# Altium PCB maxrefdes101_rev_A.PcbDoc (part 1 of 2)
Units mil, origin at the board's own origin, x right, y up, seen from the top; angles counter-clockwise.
Board outline 1192.91 x 1079.23 mil, 4 copper layers (Top Layer, Power Plane, Ground Plane, Bottom Layer), stack 32.372 mil thick; 87 components, 63 nets, 389 pads, 163 vias.
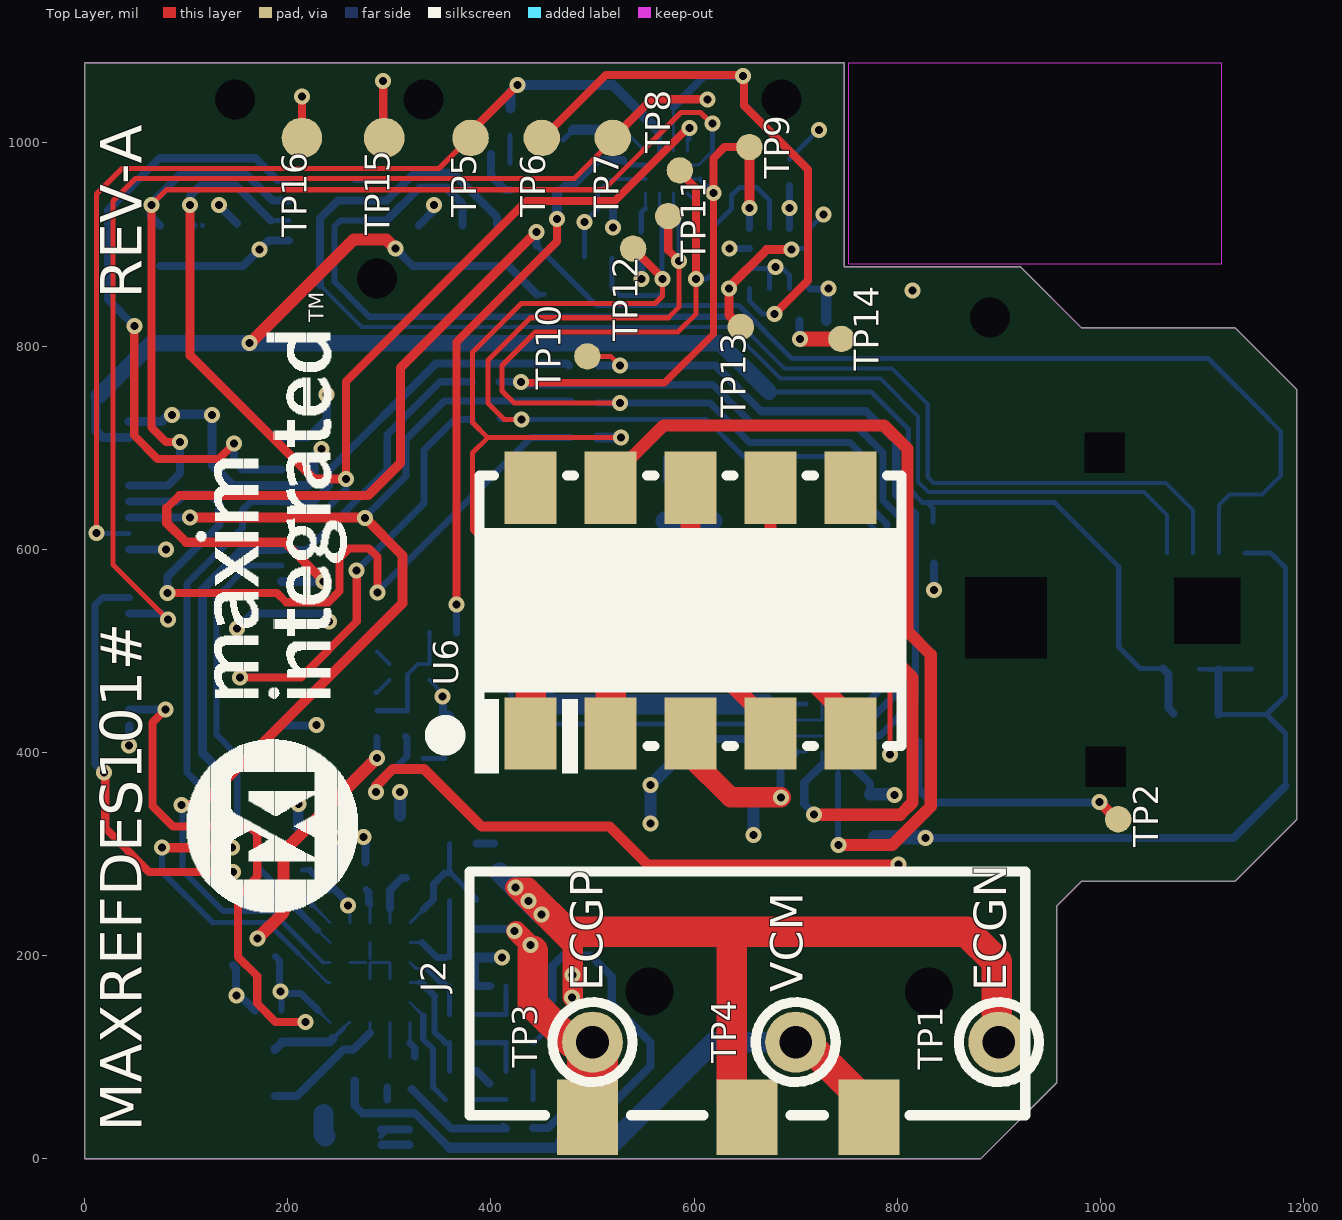
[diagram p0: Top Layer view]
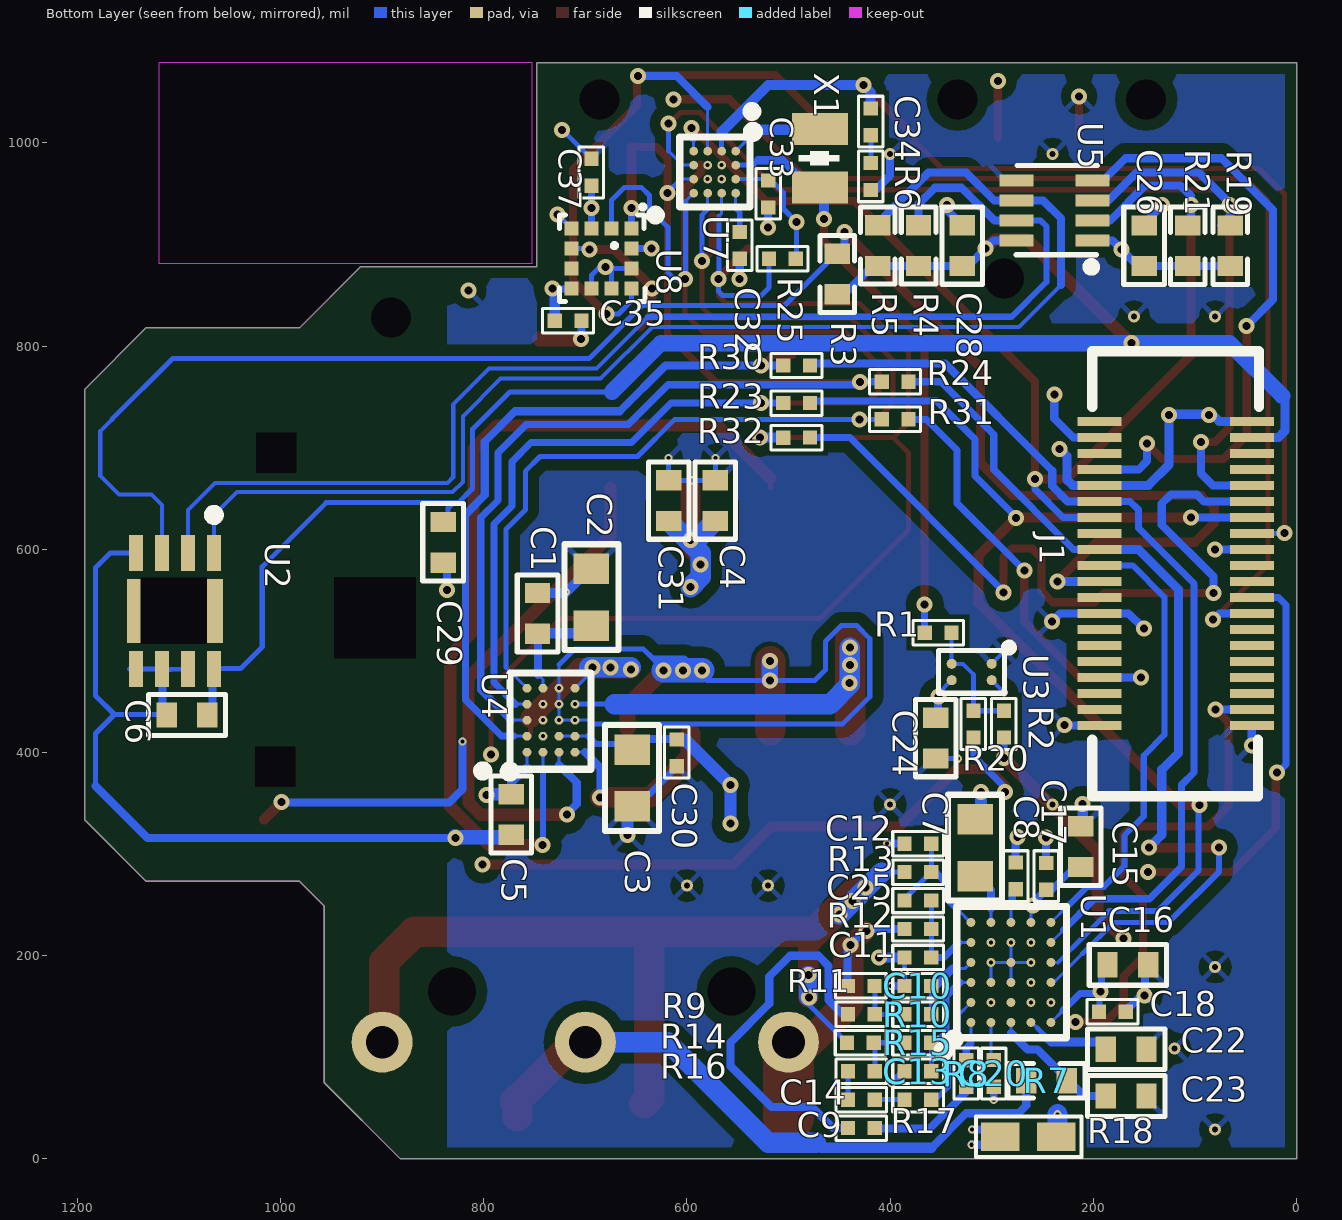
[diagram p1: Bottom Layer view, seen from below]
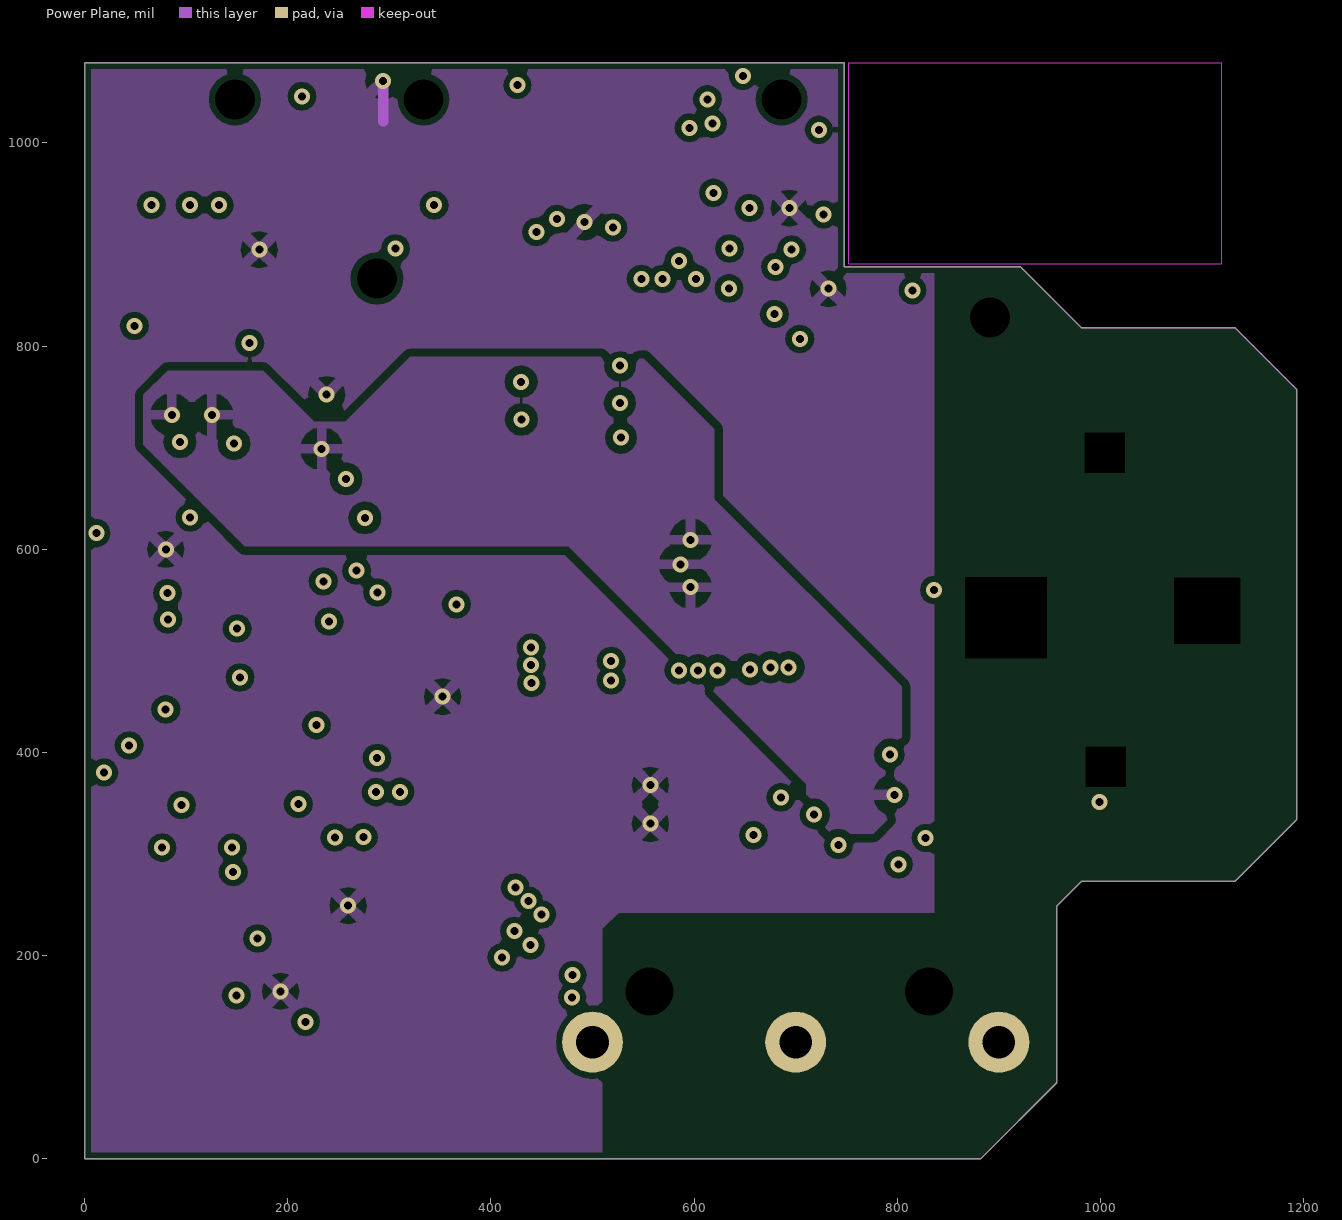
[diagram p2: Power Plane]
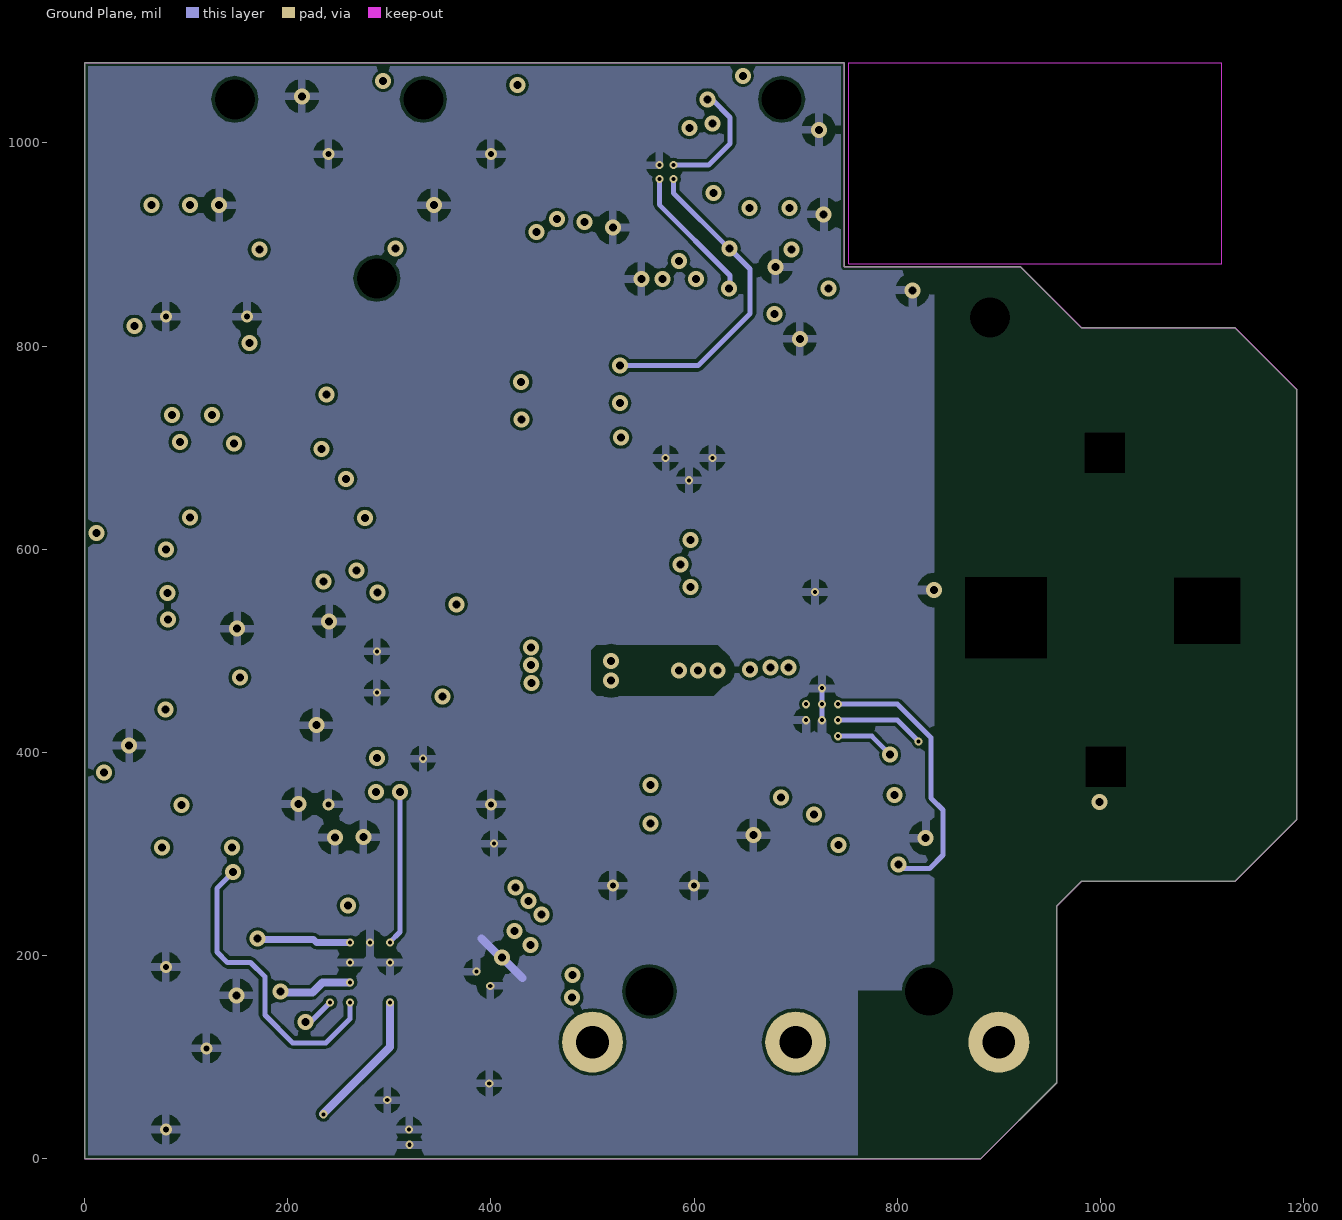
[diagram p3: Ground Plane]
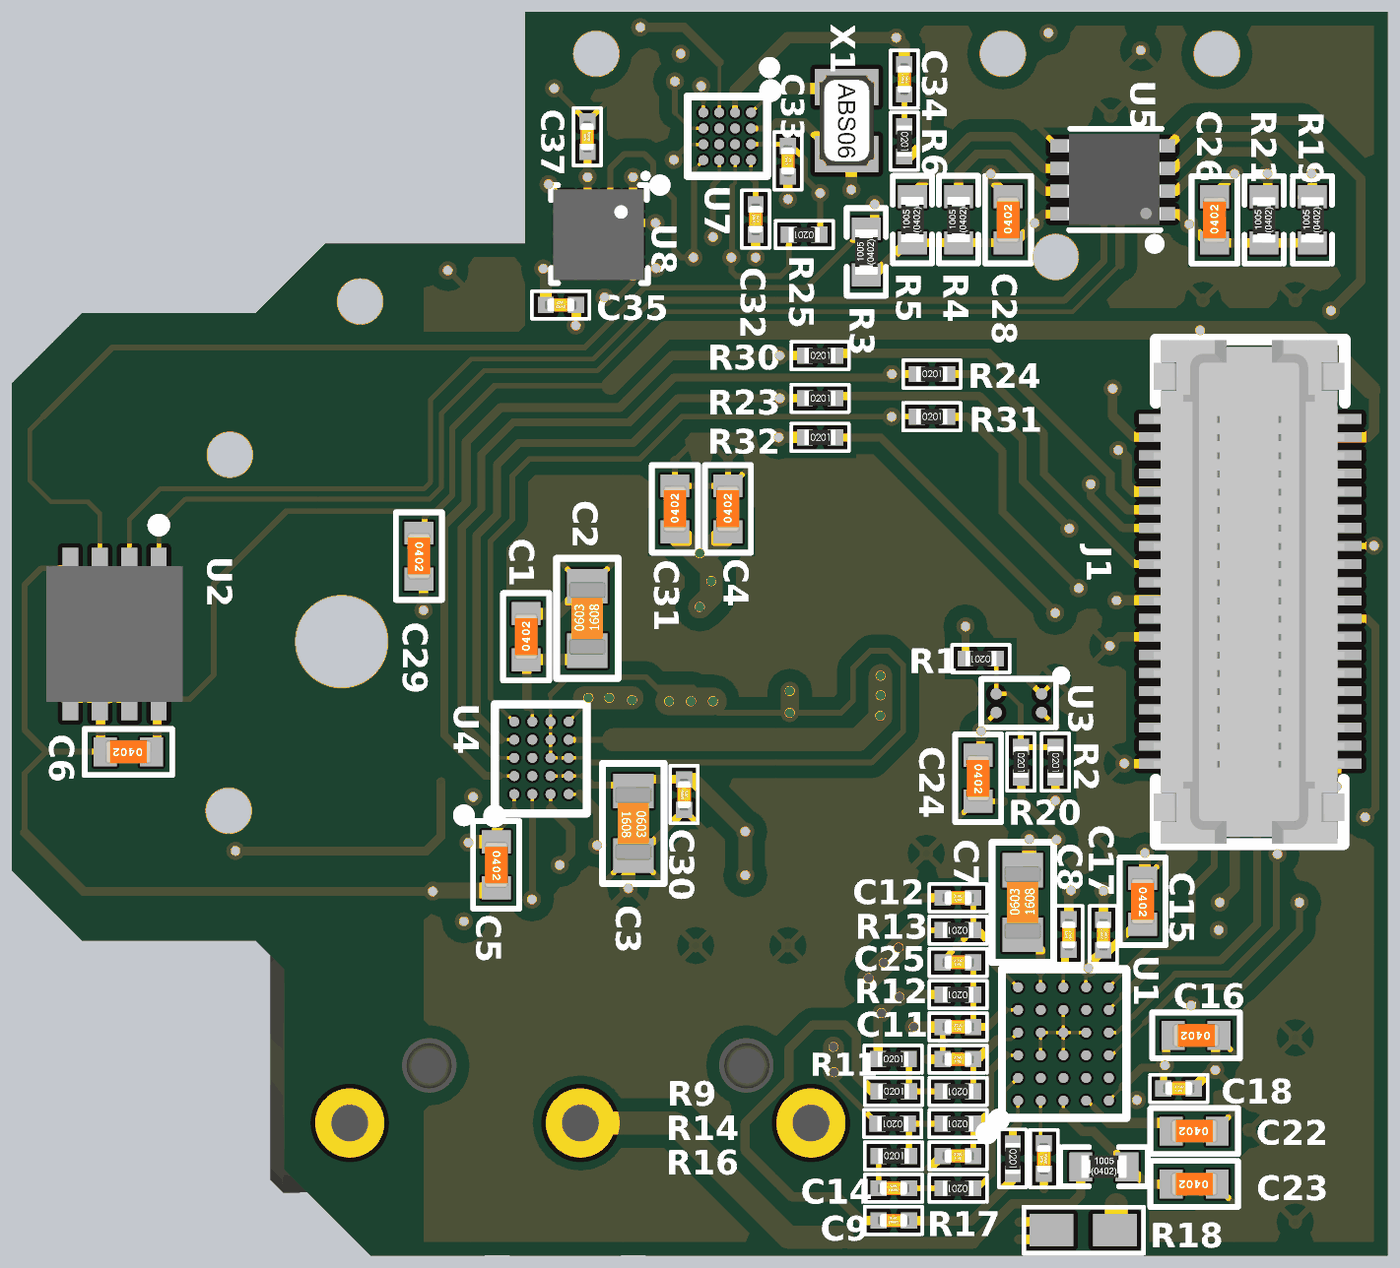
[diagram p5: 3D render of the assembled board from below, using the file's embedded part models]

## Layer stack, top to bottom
Top Solder: solder mask 0.4, Solder Resist, Dk 3.5
Top Layer: signal copper 1.4
Dielectric1: prepreg 6.8898, FR-4, Dk 4.2
Power Plane: signal copper 1.4
Dielectric2: core 12.9921, FR-4, Dk 4.2
Ground Plane: signal copper 1.4
Dielectric5: prepreg 6.8898, FR-4, Dk 4.2
Bottom Layer: signal copper 1.4
Bottom Solder: solder mask 0.4, Solder Resist, Dk 3.5

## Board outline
0,0 0,1079.23 748,1079.23 748,878.39 920.91,878.39 981.39,817.91 1132.39,817.91 1192.91,757.39 1192.91,333.91 1132.39,273.39 981.39,273.39 957,249 957,75 882,0

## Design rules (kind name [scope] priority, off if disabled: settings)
Clearance Clearance_2 [InNamedPolygon('COMPONENT_GND')] p1: gap=11 ignorepadtopadclearanceinfootprint=FALSE except(0: Arc-Hole Track-Hole SMDPad-Hole THPad-Hole Via-Hole Fill-Hole Poly-Hole Region-Hole Text-Hole)
Clearance Clearance_1 [InNamedPolygon('PLANE_5V')] p2: gap=8 ignorepadtopadclearanceinfootprint=FALSE except(0: Arc-Hole Track-Hole SMDPad-Hole THPad-Hole Via-Hole Fill-Hole Poly-Hole Region-Hole Text-Hole)
Clearance Clearance_PD_Shield [InNamedPolygon('PLANE_1V8')] p3: gap=6 ignorepadtopadclearanceinfootprint=FALSE except(0: Arc-Hole Track-Hole SMDPad-Hole THPad-Hole Via-Hole Fill-Hole Poly-Hole Region-Hole Text-Hole)
Clearance "Clearance_Bottom Layer" [OnLayer('Bottom Layer')] p4: gap=5 ignorepadtopadclearanceinfootprint=FALSE except(0: Arc-Hole Track-Hole SMDPad-Hole THPad-Hole Via-Hole Fill-Hole Poly-Hole Region-Hole Text-Hole)
Clearance "Clearance Power Plane" [OnLayer('Power Plane 1.8v')] p5: gap=5 ignorepadtopadclearanceinfootprint=FALSE except(0: Arc-Hole Track-Hole SMDPad-Hole THPad-Hole Via-Hole Fill-Hole Poly-Hole Region-Hole Text-Hole)
Clearance "Clearance Ground Plane" [(OnLayer('Ground Plane +') AND InNamedPolygon('GND'))] p6: gap=5 ignorepadtopadclearanceinfootprint=FALSE except(0: Arc-Hole Track-Hole SMDPad-Hole THPad-Hole Via-Hole Fill-Hole Poly-Hole Region-Hole Text-Hole)
Clearance [All] p7: gap=3 ignorepadtopadclearanceinfootprint=FALSE except(0: Arc-Hole Track-Hole SMDPad-Hole THPad-Hole Via-Hole Fill-Hole Poly-Hole Region-Hole Text-Hole)
ComponentClearance [All] p1: gap=0 collisioncheckmode=3 verticalgap=0 showdistances=FALSE
HoleSize [All] p1: absolutevalues=TRUE maxlimit=500 minlimit=4 maxpercent=80.000 minpercent=20.000
HoleToHoleClearance [All] p1: gap=9 allowstackedmicrovias=TRUE
MinimumAnnularRing [All] p1: minimumring=2
MinimumSolderMaskSliver [All] p1: minsoldermaskwidth=0
PlaneConnect [All] p1: planeconnectstyle=Relief reliefexpansion=20 reliefentries=4 reliefconductorwidth=7 reliefairgap=10
PolygonConnect PolygonConnect_5 [All vs IsNamedPolygon('PLANE_5V')] p1: connectstyle=Relief reliefconductorwidth=10 reliefentries=4 polygonreliefangle="90 Angle" airgapwidth=13
PolygonConnect PolygonConnect_4 [All vs IsNamedPolygon('PLANE_GROUND')] p2: connectstyle=Relief reliefconductorwidth=8 reliefentries=4 polygonreliefangle="90 Angle" airgapwidth=9
PolygonConnect PolygonConnect_3 [All vs IsNamedPolygon('PP_5V')] p3: connectstyle=Relief reliefconductorwidth=14 reliefentries=4 polygonreliefangle="90 Angle" airgapwidth=10
PolygonConnect PolygonConnect_2 [All vs IsNamedPolygon('PP_1V8')] p4: connectstyle=Relief reliefconductorwidth=10 reliefentries=4 polygonreliefangle="90 Angle" airgapwidth=8
PolygonConnect PolygonConnect_1 [All vs IsNamedPolygon('PLANE_1V8')] p5: connectstyle=Relief reliefconductorwidth=11 reliefentries=4 polygonreliefangle="45 Angle" airgapwidth=10
PolygonConnect [All] p6: connectstyle=Relief reliefconductorwidth=5 reliefentries=4 polygonreliefangle="45 Angle" airgapwidth=10
RoutingVias [All] p1: holewidth=8 width=16 viastyle="Through Hole" minholewidth=4 minwidth=8 maxholewidth=28 maxwidth=50
SilkToSilkClearance [All] p1: silktosilkclearance=0
SilkToSolderMaskClearance SilkscreenOverComponentPads [IsPad] p1: minsilkscreentomaskgap=4 clearancetoexposedcopper=TRUE
SolderMaskExpansion [All] p1: expansion=4
Width [All] p1: maxlimit=100 minlimit=3 preferedwidth=5 minimp=50.000000 maximp=50.000000 favimp=50.000000
23 further rules are at their usual default settings.

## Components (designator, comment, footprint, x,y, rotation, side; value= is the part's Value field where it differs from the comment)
C1 "10u" CAPACITOR_SMD_0402 747,517 r90 bottom
C2 "1u" CAPACITOR_SMD_0603 694,553 r90 bottom
C3 "100n" CAPACITOR_SMD_0603 654,375 r270 bottom
C4 "22u" CAPACITOR_SMD_0402 572,628 r90 bottom
C5 "22u" CAPACITOR_SMD_0402 773,359 r270 bottom
C6 "100n" CAPACITOR_SMD_0402 1072,437 r0 bottom
C7 "1u" CAPACITOR_SMD_0603 316.39,306.39 r90 bottom
C8 "1n" CAPACITOR_SMD_0201 276.39,265.39 r90 bottom
C9 "47p" CAPACITOR_SMD_0201 441.39,30.39 r180 bottom
C10 "10p" CAPACITOR_SMD_0201 359.39,170.39 r0 bottom
C11 "10p" CAPACITOR_SMD_0201 359.39,198.39 r0 bottom
C12 "10p" CAPACITOR_SMD_0201 359.39,310.39 r0 bottom
C13 "10p" CAPACITOR_SMD_0201 359.39,86.39 r0 bottom
C14 "47n" CAPACITOR_SMD_0201 441.39,58.39 r180 bottom
C15 "10u" CAPACITOR_SMD_0402 212.39,327.39 r270 bottom
C16 "10u" CAPACITOR_SMD_0402 146,191 r0 bottom
C17 "100n" CAPACITOR_SMD_0201 246.4,291.39 r270 bottom
C18 "100n" CAPACITOR_SMD_0201 168,145 r0 bottom
C20 "1u" CAPACITOR_SMD_0201 298,71 r90 bottom
C22 "10u" CAPACITOR_SMD_0402 147.62,108 r0 bottom
C23 "10u" CAPACITOR_SMD_0402 147.62,62 r0 bottom
C24 "100n" CAPACITOR_SMD_0402 355,434.19 r270 bottom
C25 "1000p C0G" CAPACITOR_SMD_0201 359.39,254.39 r0 bottom
C26 "100n" CAPACITOR_SMD_0402 150,878.87 r90 bottom
C28 "100n" CAPACITOR_SMD_0402 329.07,879 r90 bottom
C29 "10u" CAPACITOR_SMD_0402 840,627 r270 bottom
C30 "1u" CAPACITOR_SMD_0201 610,413 r270 bottom
C31 "22u" CAPACITOR_SMD_0402 618,628 r90 bottom
C32 "1u" CAPACITOR_SMD_0201 548,912.39 r270 bottom
C33 "1u" CAPACITOR_SMD_0201 520,963 r270 bottom
C34 "1u" CAPACITOR_SMD_0201 419,1034 r270 bottom
C35 "100n" CAPACITOR_SMD_0201 730,825 r180 bottom
C37 "100n" CAPACITOR_SMD_0201 694,958 r90 bottom
J1 "500913-0402" 500913-0402_MRR 194,726 r270 bottom (schematic designator J10)
J2 "SJ2-3573A2-SMT-TR" CONN_SJ2-3573A2-SMT-TR 772,33 r180 top
R1 "0R" RESISTOR_SMD_0201 352.78,518 r0 bottom
R2 "0R" RESISTOR_SMD_0201 288,428 r270 bottom
R3 "3K3" RESISTOR_SMD_0402 452,851 r90 bottom
R4 "3K3" RESISTOR_SMD_0402 372,879 r90 bottom
R5 "3K3" RESISTOR_SMD_0402 412,879 r90 bottom
R6 "10R" RESISTOR_SMD_0201 419,967 r270 bottom
R7 "499K" RESISTOR_SMD_0402 266,77 r180 bottom
R8 "0R" RESISTOR_SMD_0201 325,84 r270 bottom
R9 "0R" RESISTOR_SMD_0201 428.19,142.39 r180 bottom
R10 "2K49" RESISTOR_SMD_0201 372.58,142.39 r0 bottom
R11 "0R" RESISTOR_SMD_0201 428.58,170.39 r180 bottom
R12 "1M" RESISTOR_SMD_0201 372.58,226.39 r0 bottom
R13 "1M" RESISTOR_SMD_0201 372.58,282.39 r0 bottom
R14 "0R" RESISTOR_SMD_0201 429.19,114.39 r0 bottom
R15 "2K49" RESISTOR_SMD_0201 372.58,114.39 r0 bottom
R16 "0R" RESISTOR_SMD_0201 428.19,86.39 r180 bottom
R17 "0R" RESISTOR_SMD_0201 372.58,58.39 r0 bottom
R18 "324K" RESISTOR_SMD_0603 236.46,22 r0 bottom
R19 "3K3" RESISTOR_SMD_0402 65.14,878.87 r90 bottom
R20 "0R" RESISTOR_SMD_0201 318,428 r270 bottom
R21 "3K3" RESISTOR_SMD_0402 107,878.87 r90 bottom
R23 "0R" RESISTOR_SMD_0201 492,744 r180 bottom
R24 "0R" RESISTOR_SMD_0201 395,765 r180 bottom
R25 "10K" RESISTOR_SMD_0201 506,886 r0 bottom
R30 "0R" RESISTOR_SMD_0201 492,781 r180 bottom
R31 "0R" RESISTOR_SMD_0201 395,728 r180 bottom
R32 "0R" RESISTOR_SMD_0201 492,710 r180 bottom
TP1 "ECG_N" TESTPOINT_SIZE_A_NO_BODY 900,115 r0 top
TP2 "TestPoint" TESTPOINT_SIZE_B#1 1017.39,334.39 r270 top
TP3 "ECG_P" TESTPOINT_SIZE_A_NO_BODY 500,115 r0 top
TP4 "VCM" TESTPOINT_SIZE_A_NO_BODY 700,115 r0 top
TP5 "RSTN" TESTPOINT_SIZE_C#1 380,1005 r90 top
TP6 "TestPoint" TESTPOINT_SIZE_C#1 450,1005 r90 top
TP7 "TestPoint" TESTPOINT_SIZE_C#1 520,1005 r90 top
TP8 "TestPoint" TESTPOINT_SIZE_B#1 586,973 r90 top
TP9 "TestPoint" TESTPOINT_SIZE_B#1 654.39,996 r90 top
TP10 "TestPoint" TESTPOINT_SIZE_B#1 495,790 r90 top
TP11 "TestPoint" TESTPOINT_SIZE_B#1 574.56,928 r90 top
TP12 "TestPoint" TESTPOINT_SIZE_B#1 540,896.07 r90 top
TP13 "TestPoint" TESTPOINT_SIZE_B#1 646,819 r90 top
TP14 "TestPoint" TESTPOINT_SIZE_B#1 745,807.19 r90 top
TP15 "TestPoint" TESTPOINT_SIZE_C#2 295,1005 r90 top (schematic designator TP5)
TP16 "TestPoint" TESTPOINT_SIZE_B#2 214,1005 r90 top
U1 "MAX30001CWV+" "WLP30 0.5MM" 320.39,134.39 r90 bottom
U2 "MAX30205MTA+" TDFN_3x3mm 1104,539.39 r270 bottom
U3 "SIT1532AC-J5-DCC-32.768E" CSP_1.55x0.85_4pin 300,487.39 r270 bottom
U4 "MAX86140/1" WLP20_0.4MM 733.77,431.89 r90 bottom
U5 "MAX14595ETA+T" TDFN8 201,904 r90 bottom
U6 "LED_MODULE" HSP3_LEDMODULE_03 438.98,418.61 r90 top locked
U7 "MAX32664GWEZ+" WLP16_0.35mm 552,992 r270 bottom
U8 "KX122-1037" LGA-12_2x2x0.9 654.39,916 r270 bottom (schematic designator U9)
X1 "32.768KHz" CRYSTAL_2x1.2mm 469,1016 r270 bottom

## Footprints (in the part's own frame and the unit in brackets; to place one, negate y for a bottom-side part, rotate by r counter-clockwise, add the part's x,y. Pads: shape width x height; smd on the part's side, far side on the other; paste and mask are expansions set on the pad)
500913-0402_MRR [mm] "0.40mm Pitch SlimStack™ Board-to-Board Receptacle, Surface Mount, Dual Row, Vertical Stacking, Mated Height of 1.80mm, with Solder Tabs, 40 Circuits"
  rect 0.22x1.1 smd: 1(0,0) 2(0,3.81) 3(0.4,0) 4(0.4,3.81) 5(0.8,0) 6(0.8,3.81) 7(1.2,0) 8(1.2,3.81) 9(1.6,0) 10(1.6,3.81) 11(2,0) 12(2,3.81) 13(2.4,0) 14(2.4,3.81) 15(2.8,0) 16(2.8,3.81) 17(3.2,0) 18(3.2,3.81) 19(3.6,0) 20(3.6,3.81) 21(4,0) 22(4,3.81) 23(4.4,0) 24(4.4,3.81) 25(4.8,0) 26(4.8,3.81) 27(5.2,0) 28(5.2,3.81) 29(5.6,0) 30(5.6,3.81) 31(6,0) 32(6,3.81) 33(6.4,0) 34(6.4,3.81) 35(6.8,0) 36(6.8,3.81) 37(7.2,0) 38(7.2,3.81) 39(7.6,0) 40(7.6,3.81)
  silkscreen extent -1.75,-0.18 9.37,3.99, body extent -1.74,-0.22 9.36,3.98, height 1.69
CAPACITOR_SMD_0201 [mil] "SMD 0201 Chip Capacitor"
  rect 14x14 smd: 1(0,0) 2(26.39,0)
  silkscreen extent -12,-12 38,12, body extent -4,-6 30,6, height 12
CAPACITOR_SMD_0402 [mil] "0402 SMD Ceramic Capacitor"
  rect 20x25 smd mask+2: 1(0,0) 2(40,0)
  silkscreen extent -18,-20 58,20, body extent 0,-10 40,10, height 20
CAPACITOR_SMD_0603 [mil] "SMD 0603 Chip Capacitor"
  rect 30x35 smd mask+2: 1(-28,0) 2(28,0)
  silkscreen extent -52,-27 52,27, body extent -31,-16 31,16, height 31
CONN_SJ2-3573A2-SMT-TR [mil] "SJ2-3573A2-SMT-TR AUDIO JACK, 3.5 MM, RT, 3 CONDUC"
  round 0 hole 47.24 unplated: 0(-59,-132) 0(216,-132)
  rect 60x74 smd: 1(0,-8) 2(120,-8) 3(277,-8)
  silkscreen extent -154,-250 393,-10, body extent -197,-250 394,34, height 211
CRYSTAL_2x1.2mm [mm] "Abracon 2 lead crystal (2.00mm x 1.20mm)"
  rect 0.8x1.4 smd: 1(0.051,0) 2(1.524,0)
  silkscreen extent 0.61,-0.53 0.97,0.48, body extent -0.21,-0.61 1.79,0.61, height 0.6
CSP_1.55x0.85_4pin [mm] "1.55mm x 0.85mm 4 pin CSP Package"
  round 0.25 smd: 1(0,0) 2(0,-1) 3(0.41,-1) 4(0.41,0)
  silkscreen extent -0.48,-1.33 0.74,0.51, body extent -0.23,-1.27 0.64,0.28, height 0.6
HSP3_LEDMODULE_03 [mm] "LED Module for HSP3.0 (0.6mm PCB Thickness)"
  rect 1.8x1.3 smd: 1(0,0) 2(0,-2) 3(0,-4) 4(0,-6) 5(0,-8)
  rect 1.815x1.3 smd: 6(6.147,-8) 7(6.147,-6) 8(6.147,-4) 9(6.147,-2) 10(6.147,0)
  silkscreen extent -0.99,-9.27 6.45,1.4, body extent -0.3,-9.19 6.45,1.17, height 1.2
LGA-12_2x2x0.9 [mm] "LGA-12_2x2x0.9 SMD Package For Kionix KX122-1037 Accelerometer"
  rect 0.35x0.35 smd: 1(0,0) 2(0,-0.5) 3(0,-1) 4(0,-1.5) 5(0.5,-1.5) 6(1,-1.5) 7(1.5,-1.5) 8(1.5,-1) 9(1.5,-0.5) 10(1.5,0) 11(1,0) 12(0.5,0)
  silkscreen extent -0.58,-1.8 1.83,0.33, body extent -0.24,-1.76 1.76,0.24, height 0.95
RESISTOR_SMD_0201 [mil] "SMD 0201 Chip Resistor"
  rect 14x14 smd: 1(-13.19,0) 2(13.19,0)
  silkscreen extent -25,-12 25,12, body extent -14,-6 13,6, height 13
RESISTOR_SMD_0402 [mil] "SMD 0201 Chip Resistor"
  rect 20x25 smd mask+2: 1(0,0) 2(40,0)
  silkscreen extent -18,-17 58,17, body extent 0,-10 40,10, height 14
RESISTOR_SMD_0603 [mil] "SMD 0603 Chip Resistor"
  rect 38x28 smd: 1(0,0) 2(55,0)
  silkscreen extent -25,-20 79,20, body extent -9,-18 63,18, height 18
TDFN8 [mm] "TDFN8 2x2x0.75mm"
  rect 0.3x0.85 smd: 1(0,0) 2(0.5,0) 3(1,0) 4(1.5,0) 5(1.5,1.9) 6(1,1.9) 7(0.5,1.9) 8(0,1.9)
  silkscreen extent -0.75,-0.13 1.88,1.91, body extent -0.24,-0.11 1.76,1.94, height 0.75
TDFN_3x3mm [mm] "SON, 0.65mm pitch, 8 pin, 3mm X 3mm X 1.00mm H body (w/thermal tab 1.60 X 2.4mm),  IPC Medium Density"
  rect 0.9x0.35 smd: 1(-1.45,0.975) 2(-1.45,0.325) 3(-1.45,-0.325) 4(-1.45,-0.975) 5(1.45,-0.975) 6(1.45,-0.325) 7(1.45,0.325) 8(1.45,0.975)
  rect 1.6x2.4 smd: 9(0,0)
  silkscreen extent -2.52,0.85 -2.28,1.1, body extent -1.5,-1.5 1.5,1.5, height 1
TESTPOINT_SIZE_A_NO_BODY [mil] "32 mil testpoint pad"
  round 60 hole 32: TP(0,0)
  silkscreen extent -39,-39 39,39
TESTPOINT_SIZE_B#1 [mil] "32 mil testpoint pad"
  round 26 smd: TP(0,0)
  body extent -2,-2 2,2, height 1
TESTPOINT_SIZE_B#2 [mil] "SMD testpoint pad"
  round 40 smd: TP(0,0)
  body extent -2,-2 2,2, height 1
TESTPOINT_SIZE_C#1 [mil] "SMD testpoint pad"
  round 36 smd: TP(0,0)
  body extent -2,-2 2,2, height 1
TESTPOINT_SIZE_C#2 [mil] "SMD testpoint pad"
  round 40 smd: TP(0,0)
  body extent -2,-2 2,2, height 1
WLP16_0.35mm [mm] "WLP-16,  1.6mm x 1.6mm, 0.35mm pitch"
  round 0.22 smd mask+0.05: A1(0,0) A2(0.35,0) A3(0.7,0) A4(1.05,0) B1(0,-0.35) B2(0.35,-0.35) B3(0.7,-0.35) B4(1.05,-0.35) C1(0,-0.7) C2(0.35,-0.7) C3(0.7,-0.7) C4(1.05,-0.7) D1(0,-1.05) D2(0.35,-1.05) D3(0.7,-1.05) D4(1.05,-1.05)
  round 0.025 on Mech4 mask+0.051: ""(-0.022,-0.022) ""(-0.022,0.022) ""(0.022,-0.022) ""(0.022,0.022)
  silkscreen extent -0.61,-1.4 1.4,0.56, body extent -0.18,-1.22 1.22,0.18, height 0.63
WLP20_0.4MM [mil] "WLP-20,  5x4, 0.4mm pitch"
  round 8.66 smd mask+1.97: A1(-31.5,23.62) A2(-15.75,23.62) A3(0,23.62) A4(15.75,23.62) A5(31.5,23.62) B1(-31.5,7.87) B2(-15.75,7.87) B3(0,7.87) B4(15.75,7.87) B5(31.5,7.87) C1(-31.5,-7.87) C2(-15.75,-7.87) C3(0,-7.87) C4(15.75,-7.87) C5(31.5,-7.87) D1(-31.5,-23.62) D2(-15.75,-23.62) D3(0,-23.62) D4(15.75,-23.62) D5(31.5,-23.62)
  round 1 on Mech4 mask+2: ""(-32.38,-24.51) ""(-32.38,-8.76) ""(-32.38,6.99) ""(-32.38,22.74) ""(-32.38,-22.74) ""(-32.38,-6.99) ""(-32.38,8.76) ""(-32.38,24.51) ""(-30.61,-24.51) ""(-30.61,-22.74) ""(-30.61,-8.76) ""(-30.61,-6.99) ""(-30.61,6.99) ""(-30.61,8.76) ""(-30.61,22.74) ""(-30.61,24.51) ""(-16.63,-24.51) ""(-16.63,-8.76) ""(-16.63,6.99) ""(-16.63,22.74) ""(-16.63,-22.74) ""(-16.63,-6.99) ""(-16.63,8.76) ""(-16.63,24.51) ""(-14.86,-24.51) ""(-14.86,-22.74) ""(-14.86,-8.76) ""(-14.86,-6.99) ""(-14.86,6.99) ""(-14.86,8.76) ""(-14.86,22.74) ""(-14.86,24.51) ""(-0.88,-24.51) ""(-0.88,-8.76) ""(-0.88,6.99) ""(-0.88,22.74) ""(-0.88,-22.74) ""(-0.88,-6.99) ""(-0.88,8.76) ""(-0.88,24.51) ""(0.88,-24.51) ""(0.88,-22.74) ""(0.88,-8.76) ""(0.88,-6.99) ""(0.88,6.99) ""(0.88,8.76) ""(0.88,22.74) ""(0.88,24.51) ""(14.86,-24.51) ""(14.86,-8.76) ""(14.86,6.99) ""(14.86,22.74) ""(14.86,-22.74) ""(14.86,-6.99) ""(14.86,8.76) ""(14.86,24.51) ""(16.63,-24.51) ""(16.63,-22.74) ""(16.63,-8.76) ""(16.63,-6.99) ""(16.63,6.99) ""(16.63,8.76) ""(16.63,22.74) ""(16.63,24.51) ""(30.61,-24.51) ""(30.61,-8.76) ""(30.61,6.99) ""(30.61,22.74) ""(30.61,-22.74) ""(30.61,-6.99) ""(30.61,8.76) ""(30.61,24.51) ""(32.38,-24.51) ""(32.38,-22.74) ""(32.38,-8.76) ""(32.38,-6.99) ""(32.38,6.99) ""(32.38,8.76) ""(32.38,22.74) ""(32.38,24.51)
  silkscreen extent -55,-39 47,46, body extent -38,-30 39,31, height 25
"WLP30 0.5MM" [mm] "WLP 30 0.5mm Pitch"
  round 0.22 smd mask+0.05: A1(0,0) A2(0.5,0) A3(1,0) A4(1.5,0) A5(2,0) A6(2.5,0) B1(0,-0.5) B2(0.5,-0.5) B3(1,-0.5) B4(1.5,-0.5) B5(2,-0.5) B6(2.5,-0.5) C1(0,-1) C2(0.5,-1) C3(1,-1) C4(1.5,-1) C5(2,-1) C6(2.5,-1) D1(0,-1.5) D2(0.5,-1.5) D3(1,-1.5) D4(1.5,-1.5) D5(2,-1.5) D6(2.5,-1.5) E1(0,-2) E2(0.5,-2) E3(1,-2) E4(1.5,-2) E5(2,-2) E6(2.5,-2)
  round 0.025 on Mech4 mask+0.051: ""(-0.022,-0.022) ""(-0.022,0.022) ""(0.022,-0.022) ""(0.022,0.022)
  silkscreen extent -0.84,-2.38 2.9,0.81, body extent -0.18,-2.18 2.67,0.18, height 0.63

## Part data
C1 C15 C16 C22 C23 C29: library part CAP_0402_10u, "CAP CER 10UF 4V X5R 0402"
C2 C7: library part CAP_0603_1u, "CAP CER 1UF 16V X5R 0603"
C3: library part CAP_0603_100n, "CAP CER 0.1UF 16V X7R 0603"
C4 C5 C31: library part CAP_0402_22U, "CAP CER 22UF 6.3V X5R 0402"
C6 C24 C26 C28: library part CAP_0402_100n, "CAP CER 0.1UF 16V X7R 0402"
C8: library part CAP_0201_1n, "CAP CER 1000PF 16V X7R 0201"
C9: library part CAP_0201_47p, "CAP CER 47PF 25V C0G/NP0 0201"
C10 C11 C12 C13: library part CAP_0201_10p, "CAP CER 10PF 25V C0G/NP0 0201"
C14: library part CAP_0201_47n, "CAP CER 0.047UF 16V X5R 0201"
C17 C18 C35 C37: library part CAP_0201_100n, "CAP CER 0.1UF 10V X5R 0201"
C20 C30 C32 C33 C34: library part CAP_0201_1u, "CAP CER 1UF 10V X6S 0201"
C25: library part CAP_0201_1000p, "CAP CER 1000PF 25V C0G/NP0 0201"
J1: library part MOLEX_5009130402, "CONN RCPT 40POS 0.4MM SMD GOLD"
J2: "AUDIO JACK, 3.5 MM, RT, 3 CONDUC"
R1 R2 R8 R9 R11 R14 R16 R17 R20 R23 R24 R30 R31 R32: library part RES_0201_0R, "RES SMD 0 OHM JUMPER 1/20W 0201"
R3 R4 R5 R19 R21: library part RES_0402_3K3, "RES SMD 3.3K OHM 1% 1/10W 0402"
R6: library part RES_0201_10R, "RES SMD 10 OHM 1% 1/20W 0201"
R7: library part RES_0402_499K, "RES SMD 49.9K OHM 1% 1/10W 0402"
R10 R15: library part RES_0201_2K49, "RES SMD 2.49K OHM 1% 1/20W 0201"
R12 R13: library part RES_0201_1M, "RES SMD 1M OHM 1% 1/20W 0201"
R18: library part RES_0603_324K%0.1_10ppm, "RES SMD 324K OHM 0.1% 1/16W 0603"
R25: library part RES_0201_10K, "RES SMD 10K OHM 1% 1/20W 0201"
TP1 TP3 TP4 TP5: library part TestPoint, "PCB Pad Test Point"
TP2 TP6 TP7 TP8 TP9 TP10 TP11 TP12 TP13 TP14 TP15 TP16: "PCB Pad Test Point"
U1: "Ultra-Low Power Single Channel Integrated Biopotential (ECG, Pace, R-R Detection) and Bioimpedance (BioZ) AFE"
U2: "Human Body Temperature Sensor"
U3: "OSC MEMS 32.768KHZ LVCMOS SMD"
U4: "Best-in-Class Optical Pulse Oximeter and Heart Rate Sensor for Wearable Health"
U5: "Low-Power Dual-Channel Logic-Level Translator"
U6: library part HSP3_LEDMODULE_03, "MAXREFDES101 LED Module v4 PCB"
U7: library part MAX32660GWE+, "Ultra-Low Power Biometric Sensor Hub"
U8: "ACCELEROMETER 2-8G I2C/SPI 12LGA"
X1: library part CRYSTAL_ABS06-107-32.768KHZ-T, "CRYSTAL 32.7680KHZ 4PF SMD"

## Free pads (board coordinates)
  round 0 hole 39.37: 0(148,1043) 0(287.75,866.66) 0(333.62,1043) 0(686.2,1043) 0(891,828)
  rect 0x0 hole 80 square: 0(907,532.82)
  rect 0x0 hole 39.37 square: 0(1004,695) 0(1005,386)
  rect 0x0 hole 65 square: 0(1105,539.39)

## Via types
v1: diameter 15.75, hole 7.87, Top Layer to Bottom Layer, tented both sides, 114 vias
v2: diameter 8, hole 4, Ground Plane to Bottom Layer, 23 vias
v3: diameter 8, hole 4, Ground Plane to Bottom Layer, tented bottom, 14 vias
v4: diameter 11.81, hole 5.91, Ground Plane to Bottom Layer, tented bottom, 11 vias
v5: diameter 15.75/15.75/15.75/15.75 (per signal layer), hole 7.87, Top Layer to Bottom Layer, tented both sides, 1 vias

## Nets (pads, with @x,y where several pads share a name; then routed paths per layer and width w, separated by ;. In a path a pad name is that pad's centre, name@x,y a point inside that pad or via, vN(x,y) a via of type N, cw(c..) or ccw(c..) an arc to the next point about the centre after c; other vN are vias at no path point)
1V8: C3.1 C15.2 C16.2 C17.2 C18.2 C24.1 C26.1 C30.1 C33.1 C35.1 C37.1 J1.3 J1.18 R19.1 R21.1 R25.1 TP15.TP U1.D3 U1.D6 U1.E1 U3.3 U4.C2 U4.D2 U5.1 U7.A3 U8.3 U8.7 | length 1091.8
  Top Layer w8: TP15.TP@294,1005 v1(294,1061)
  Power Plane w10: 294,1021.46 v1(294,1061)
  Ground Plane w8: v1@193,162.39 194.61,164 224.23,164 234.11,173.89 v2(261.14,173.89)
  Bottom Layer w3: 229.71,146.32 U1.E1@241.65,134.39 ; U1.D6@261.33,232.81 v1@261.33,245.44 ; 697.14,416.14 U4.D2@710.14,416.14 U4.C2@725.89,416.14
  Bottom Layer w4: U3.3@339.37,471.25 v1@352.78,457.84 ; C33.1@520,964.44 U7.A3@552,964.44
  Bottom Layer w5: v1@193.78,162.39 v1@194.09,162.08 ; C15.2@214.39,284.39 C15.2@221.39,284.39 ; C17.2@240.78,265 C17.2@246.4,265 ; v1@260.39,246.39 v1@261.33,245.44 ; R25.1@492,888 v1(492,922) 505,935 505,951 517,963 C33.1@520,963 ; C30.1@614.39,416.39 617.44,413.34 ; C3.1@660.44,413.34 C3.1@665.39,408.39 ; v1@731.39,856.39 v1@732.39,855.39
  Bottom Layer w6: C18.2@194.09,146 v1@194.09,162.08 ; C3.1@665.39,408.39 689.39,408.39 697.14,416.14
  Bottom Layer w7: C16.2@188,199.22 191.83,195.39 191.83,166.17 195,163 213.04,163 229.71,146.32 ; C15.2@221.39,284.39 C17.2@240.78,265 ; U8.3@693.76,916 C37.1@693.76,958 ; U8.7@713.44,856.94 714,856.39 v1@730,856.39
  Bottom Layer w8: J1.18@44,600.02 69.5,600.02 v1(80,600) ; R19.1@74.14,878.87 155.87,878.87 181,904 U5.1@201,904 ; J1.3@194,710.25 219.77,710.25 238.39,728.88 v1(238.39,752.39) ; C17.2@246.4,265 260.39,251.01 v1@260.39,246.39 ; C24.1@352.78,432 v1@352.78,457.84 ; 617.44,413.34 C3.1@660.44,413.34
  Bottom Layer w10: C35.1@730,825 v1@730,856.39
  Bottom Layer w12: v1@557,334.78 557,368.16 601.84,413 C30.1@610,413
  Bottom Layer w14: C24.1@355,434.19 C24.1@357.19,434.19
  other v1: 193,165 259.39,249.39 557,330 557,368 352.39,455 732.22,856.56 172,895 693.76,936
3V: C6.1 C28.1 C29.1 J1.4 R3.1 R4.1 R5.1 U2.8 U5.8 | length 1802.3
  Top Layer w12: v1@162.55,802.55 265,905 297.07,905 v1(306,896.07)
  Bottom Layer w5: R3.1@445.39,851 R3.1@452,851 ; 673.65,755 774.23,755 811,718.23 811,660 825,646 955,646 1018,583 1018,504 1039.23,482.77 U2.8@1061.53,482.77 ; 829.5,646 835,640.5 C29.1@835,627.13
  Bottom Layer w8: U5.8@281.3,903.87 298.21,903.87 v1(306,896.07) 323.07,879 C28.1@329.07,879 R4.1@372,879 R5.1@406,879 ; R5.1@412,879 417.39,879 R3.1@445.39,851 ; U2.8@1061.53,482.77 1067,477.3 1067,443.78 C6.1@1072,438.77
  Bottom Layer w9: 16,754 11.39,749.39 11.39,716.5 17.64,710.25 J1.4@44,710.25
  Bottom Layer w16: 14.06,751.06 66,803 625.65,803 673.65,755
  other v1: 162.55,803
5V: C4.1 C5.1 C31.1 J1.2 J1.9 U4.A1 U6.8 | length 573.3
  Top Layer w20: v1@586.33,585.35 586.33,573 v1(596.46,562.87) ; v1(586.46,585.35) 586.46,592.46 597,603 v1@597,608 ; v1(596.46,609.35) U6.8@596.46,660.62
  Bottom Layer w3: 757.39,385.44 U4.A1@757.39,400.39 U4.A1@757.61,400.39
  Bottom Layer w5: C31.1@618,627.87 C31.1@618,628 ; v1@796.35,359 v1(797,358.35)
  Bottom Layer w7: v1@124,733 v1@125.39,734.39 ; J1.9@197,663 J1.9@198,664
  Bottom Layer w8: 757.39,385.44 773,369.83 C5.1@773,359
  Bottom Layer w9: J1.2@44,726 76,726 83,733 v1@124,733 ; v1@125.39,734.39 125.39,683.51 145.9,663 J1.9@197,663 ; J1.9@194,663.01 220.27,663.01 226,668.74 226,692 v1@233.26,699.26
  Bottom Layer w12: C5.1@773,359 v1@796.35,359
  Bottom Layer w20: C4.1@572,628 v1@593,607 ; v1(596.46,562.87) 586.46,572.87 v1(586.46,585.35) 586.46,596.33 v1@597.13,607 ; v1@597.97,607.84 C31.1@618,627.87
  other v1: 233.51,699 86,732.39 125.39,732.39
BI_N: C13.1 R15.1 U1.A3 | length 108.1
  Bottom Layer w3: U1.A3@320.39,173.89 330.89,173.89
  Bottom Layer w5: C13.1@359.39,86.39 R15.1@359.39,114.39
  Bottom Layer w6: 344.39,160.39 344.39,125.39 R15.1@355.39,114.39
  Bottom Layer w7: 330.89,173.89 344.39,160.39
BI_P: C10.1 R10.1 U1.A4 | length 72.5
  Bottom Layer w3: U1.A4@320.39,193.44 326.44,187.39 338.39,187.39
  Bottom Layer w5: R10.1@359.39,142.39 C10.1@359.39,170.39
  Bottom Layer w8: 338.39,187.39 C10.1@355.39,170.39
DRV_N: R17.1 U1.A2 | length 110.2
  Bottom Layer w3: U1.A2@320.39,154.07 333.39,141.07
  Bottom Layer w5: 343,70.78 R17.1@355.39,58.39
  Bottom Layer w6: 333.39,141.07 333.39,118 343,108.39 343,70.78
DRV_P: R8.1 U1.A1 | length 36.1
  Bottom Layer w3: 320.39,113.98 U1.A1@320.39,134.39
  Bottom Layer w7: 320.39,113.98 325,109.36 325,100.78 R8.1@325.39,100.39
ECG_INT: J1.24 U1.D2 | length 707.7
  Top Layer w8: v1@20.39,382.39 20.39,325.61 63.61,282.39 v1(146.39,282.39)
  Ground Plane w5: v1(146.39,282.39) 130.36,266.36 130.36,203.64 140.56,193.44 163.49,193.44 177.56,179.37 177.56,141.62 204.95,114.23 237.55,114.23 261.14,137.82 v2@261.14,154.07
  Bottom Layer w7: v1@18.89,379.89 10.39,388.39 10.39,545.39 17.77,552.77 J1.24@44,552.77
  other v1: 19.39,380.39
  other v2: 261.33,154.07
ECG_INT2: J1.38 U1.E2 | length 522.7
  Top Layer w8: v1(79.96,442.55) 67,429.6 67,347.39 87,327.39 162.39,327.39 170,319.78 170,278.08 151,259.08 151,199 170,180 170,153 188,135 214.78,135 v1@217.39,132.39
  Ground Plane w5: v1@217.39,132.39 219.96,132.39 v2(241.65,154.07)
  Bottom Layer w5: v1@79.84,442.54 v1@80,442.7
  Bottom Layer w8: J1.38@44,442.54 v1@79.84,442.54
  other v1: 217.39,135
ECG_N: J2.2 R13.2 R14.2 TP1.TP | length 1056.4
  Top Layer w20: v1@480.5,159 480.5,210.5 423.83,267.17 436.83,267.17 480.5,223.5
  Top Layer w30: 480.5,223.5 868.5,223.5 898,194 898,127 TP1.TP@910,115 ; 637,223.5 637,60 J2.2@642,55
  Bottom Layer w5: R13.2@385.78,282.39 408.39,282.39 408.39,282 ; R14.2@442.39,114.39 480,152 v1(480,159) ; v1@480,159.5 v1@480,162
  Bottom Layer w18: v1@480.5,159.5 v1(480.5,181)
  Bottom Layer w20: 408.39,282 v1@449.81,240.58
  other v1: 450,240.78 437,254.17 424,267.17
ECG_P: J2.3 R11.1 R12.2 TP3.TP | length 326.4
  Top Layer w5: v1(423.16,224.39) v1@424.85,224.39 ; v1@438.84,207 v1(438.84,210.41)
  Top Layer w20: v1@424.85,224.39 v1(438.84,210.41) ; TP3.TP@479,115 TP3.TP@500,115
  Top Layer w30: v1@441,204.84 441,153 TP3.TP@479,115
  Top Layer w50: J2.3@500,41 TP3.TP@500,115
  Bottom Layer w8: R12.2@385.78,226.39 422.86,226.39 v1(438.84,210.41) 441.78,207.47 R11.1@441.78,170.39
FCLK: R1.1 R2.1 R20.1 U3.2 | length 122.2
  Bottom Layer w4: 318,477 328.39,487.39 U3.2@339.37,487.39 R1.1@339.37,517.79
  Bottom Layer w5: R2.1@288,441.19 R20.1@318,441.19 318,477 ; R1.1@339.37,517.79 R1.1@339.58,518
FCLK_ECG: R2.2 U1.D5 | length 335.8
  Top Layer w12: v1(170.39,217) 196,242.61 196,303 287.81,394.81 v1@287.81,396.19
  Ground Plane w7: v1@174.63,216 225.29,216 228.29,213 v2@261.33,213
  Bottom Layer w7: v1(288,394.78) R2.2@288,414.81
  other v2: 261.33,213.13
GND: C1.2 C2.2 C3.2 C4.2 C5.2 C6.2 C8.2 C10.2 C11.2 C12.2 C13.2 C15.1 C16.1 C17.1 C18.1 C20.1 C22.1 C23.1 C24.2 C26.2 C28.2 C29.2 C30.2 C31.2 C32.2 C33.2 C35.2 C37.2 J1.25 J1.39 J1.40 R6.2 R18.2 TP14.TP TP16.TP U1.B3 U1.B4 U1.C3 U1.C4 U1.C5 U1.D4 U2.4 U2.5 U2.6 U2.7 U3.1 U3.4 U4.C3 U4.C4 U4.C5 U4.D3 U5.5 U6.2 U6.4 U7.B2 U8.4 U8.8 U8.9 U8.11 | length 3230.9
  Top Layer w8: TP16.TP@214,1005 v1(214,1046)
  Top Layer w15: v1(704,807.19) TP14.TP@745,807.19
  Top Layer w16: v1(623,481) 658.5,445.5 U6.4@658.5,424.22
  Top Layer w20: v1(585,481) v1(623,481)
  Top Layer w30: U6.2@517.85,421.77 v1@517.85,490
  Ground Plane w5: v2(725.89,431.89) v2(725.89,447.63) v2(725.89,463.38)
  Ground Plane w8: 390.81,217.19 v1@411,197 ; v1(410.78,198.39) 430.97,178.19
  Bottom Layer w3: v2(261.33,193.44) U1.C4@277.08,193.44 ; U1.C3@281.02,177.7 U1.C4@281.02,193.44 v2(300.7,193.44) U1.B3@300.7,177.7 ; U1.C4@281.02,197.38 v2(281.02,213.13) ; 691.36,428 695.25,431.89 v2(710.14,431.89) v2(725.89,431.89) v2(725.89,447.63) v2(725.89,463.38) 725.89,486.55
  Bottom Layer w4: v3(287.75,459) U3.4@300,471.25 ; v3(287.75,499.64) U3.1@300,487.39
  Bottom Layer w5: C26.2@150,918.87 C26.2@150,920.9 ; U5.5@265.94,963.06 U5.5@275.8,963.06 ; v3@287,459 v3(287.75,459) ; R18.2@291.46,22 R18.2@298,28.54 ; v3(333.17,394) 333.36,394.19 C24.2@355,394.19 ; C13.2@385.78,86.39 C13.2@386.39,86.39 ; C10.2@385.78,170.39 v2(385.78,184.39) C11.2@385.78,198.39 ; v3(572,690) C4.2@572,668 C31.2@618,668 v3(618,690) ; v1@622.44,481.56 633.94,493.05 ; C3.2@636.72,359.39 C3.2@647.65,359.39 ; U8.11@654.39,876.63 v1@675.39,876.63 ; U8.9@674.07,856.94 674.07,875.31 v1@675.39,876.63 ; 691.36,428 685.5,428 563,428 447,428 420,455 420,512.16 432.84,525 448.12,525 463.62,509.5 463.62,481.47 474.09,471 501,471 v1(518.38,471) 536,471 580.23,471 602.29,493.05 633.94,493.05 ; U8.8@693.76,856.94 693.76,869.97 687.1,876.63 v1@675.39,876.63 ; C37.2@694,984.39 694.15,984.39 v1(722.76,1013) ; U8.4@713.44,916 713.83,916 v1(727.57,929.74) ; 725.89,486.55 710.44,502 642.88,502 633.94,493.05 ; C29.2@835,587.13 C29.2@836,586.13 ; U2.7@1097.59,482.3 U2.6@1116,481.55 ; C6.2@1116,437.39 1163.39,437.39 ; U2.6@1116,482.3 U2.5@1148.77,482.3 ; U2.4@1142.39,596.48 1167.52,596.48 1182,582 1182,456 1163.39,437.39 ; 1182,367 1182,418.78 1163.39,437.39
  Bottom Layer w7: v3(298,58) C20.1@298,71 ; C30.2@610.25,385.86 C3.2@636.72,359.39
  Bottom Layer w8: v1(44,407) J1.40@44,426.79 ; v1@132.9,938 C26.2@150,920.9 ; C16.1@146,191 149.27,187.73 149.27,164.39 v1@147.39,164.39 ; v1@149.31,164.39 C18.1@167.7,146 ; v1(150.26,522.03) 165.25,537.02 J1.25@194,537.02 232.75,537.02 v1(240.78,529) ; J1.39@194,426.79 v1@228.39,426.79 ; C17.1@246.4,291.39 v1(246.4,316.39) ; C8.2@276.39,291.78 v1@276.39,316.78 ; R18.2@291.93,29 v3(319.47,29) ; R18.2@292.19,14 v3(319.73,14) ; C28.2@329.07,919 344.13,934.06 v1(344.13,938.74) ; C10.2@385.78,170.39 v3(399.39,170.39) ; C12.2@385.78,310.39 v3(403,310.39) ; C13.2@386.39,86.39 v3(398.39,74.39) ; v4(400,989) 400,968 414.19,953.81 R6.2@419,953.81 ; v1(520,916.81) C33.2@520,936.61 ; v1(548,866.19) C32.2@548,886 ; v1@703.61,807.19 C35.2@703.61,825 ; v1(828,316) 1131,316 1182,367 ; v1(836,560) C29.2@836,586.13 ; C6.2@1116,437.39 U2.6@1116,481.55
  Bottom Layer w10: C15.1@210.4,326.39 v1@210.4,346.39 ; C11.2@385.78,198.39 v1(410.78,198.39) ; C2.2@698.27,578.23 719.5,557 C1.2@747,557
  Bottom Layer w12: v1(658.39,318.67) C3.2@658.39,348.65 ; C2.2@696.39,577.39 693.39,577.39 C2.2@697.39,581.39
  Bottom Layer w14: C5.2@778,316.78 828.83,316.78 828,317.61 v1(828,316)
  Bottom Layer w16: v1(518.38,471) v1(518.38,490)
  Bottom Layer w24: v1(585,481) v1(604,481) v1(623,481)
  other v1: 149.39,161 274.41,316.78 210.39,349.39 228.18,427 815,855 680,878 132.55,938.74
  other v2: 595,668 565.78,978.22
  other v3: 719,558.11
  other v4: 80,29 120,109 80,189 520,269 600,269 240,349 400,349 80,829 160,829 240,989
I2C_SCL: J1.13 R21.2 U5.2 U7.D1 | length 1148.2
  Top Layer w5: v1(104,939) v1@104,943 ; v1@594,1015 v1(595.25,1015)
  Top Layer w8: v1(257.39,669.39) 257.39,765.39 434.88,942.88 521.88,942.88 v1@594,1015
  Top Layer w9: v1(104,939) 104,791 225.61,669.39 v1(257.39,669.39)
  Bottom Layer w3: U7.D1@593.34,992 593.34,1002.32 ; v1@593.34,1015 v1@595,1013.34
  Bottom Layer w5: R21.2@116,918.87 R21.2@116.09,918.96 ; 183.31,923.69 U5.2@201,923.69 ; 593.34,1002.32 595,1003.98 v1@595,1013.34
  Bottom Layer w7: J1.13@194,631.51 229.78,631.51 257.39,659.12 v1(257.39,669.39)
  Bottom Layer w8: R21.2@107,918.87 104,921.87 v1(104,939) 104,947.66 114.34,958 149,958 183.31,923.69
I2C_SCL_H: R4.2 U2.2 U5.7 | length 1246.3
  Bottom Layer w4: 638,829 689,778 794.71,778 830,742.71 830,671 835.61,665.39 1064.61,665.39 1091.2,638.8 U2.2@1091.2,596.48
  Bottom Layer w6: U5.7@275.8,923.69 251.87,923.69 246.08,917.89 246.08,863.33 280.41,829 638,829
  Bottom Layer w8: U5.7@275.8,923.69 297.41,923.69 329.73,956 356,956 372,940 R4.2@372,919
I2C_SDA: J1.10 R19.2 U5.3 U7.D2 | length 1172.7
  Top Layer w5: v1(65.73,939) 80.73,954 511,954 587,1030 606.27,1030 617.27,1019 v1(618,1019)
  Top Layer w8: v1@66,937 66,720 80.12,705.88 v1(93.9,705.88)
  Bottom Layer w3: U7.D2@593.34,978.22 604.29,978.22 618,991.93
  Bottom Layer w5: 618,991.93 v1@618,1018
  Bottom Layer w8: J1.10@44,663.01 82.01,663.01 93.89,674.89 v1(93.9,705.88) ; R19.2@74.14,918.87 65,928.01 65,940 96,971 157.43,971 185.06,943.37 U5.3@201,943.37
I2C_SDA_H: R5.2 U2.1 U5.6 | length 1287.3
  Bottom Layer w4: 231.96,860.11 273.08,819 634,819 685,768 783.61,768 820.57,731.03 820.57,666.43 830.61,656.39 1042.89,656.39 1065.61,633.67 U2.1@1065.61,596.48
  Bottom Layer w8: 231.96,860.11 231.96,925.96 249.37,943.37 297.48,943.37 325.11,971 362.16,971 406,927.16 R5.2@406,919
